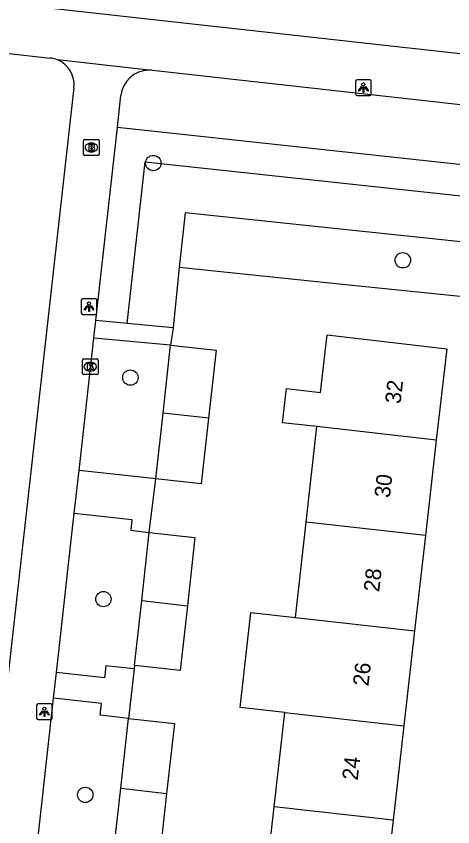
# Model space of a CAD drawing. Extents: x 161928 to 163055, y 386475 to 387428.
# Drawn here: x 162152.3 to 162180.1, y 387186 to 387237.6 of the extents above; entities that cross this region are included whole.
import ezdxf

# ---------------------------------------------------------------- set-up
doc = ezdxf.new("R2010")
doc.units = 0
for name, color, linetype in [('IMGEO_Boom', 7, 'Continuous'), ('IMGEO_Brandkraan', 7, 'Continuous'), ('IMGEO_Groenvoorziening', 7, 'Continuous'), ('IMGEO_Kolk', 7, 'Continuous'), ('IMGEO_Lichtpunt', 7, 'Continuous'), ('IMGEO_Pand', 7, 'Continuous'), ('IMGEO_Pand_nummerreeks', 7, 'Continuous'), ('IMGEO_Voetpad_open', 7, 'Continuous')]:
    doc.layers.add(name, color=color, linetype=linetype)

msp = doc.modelspace()

# ---------------------------------------------------------------- linework, layer by layer
at = {"layer": 'IMGEO_Boom'}
for centre in [(162161.043, 387228.29), (162176.933, 387222.099), (162159.581, 387214.63), (162157.866, 387200.526), (162156.71, 387188.06)]:
    msp.add_circle(centre, 0.489, dxfattribs=at)
at = {"layer": 'IMGEO_Brandkraan'}
for p, q in [((162156.596, 387228.856), (162156.596, 387229.708)), ((162156.671, 387229.782), (162157.523, 387229.782)), ((162157.597, 387229.708), (162157.597, 387228.856)), ((162157.084, 387229.562), (162157.109, 387229.562)), ((162157.523, 387228.782), (162156.671, 387228.782)), ((162157.107, 387229.002), (162157.082, 387229.002))]:
    msp.add_line(p, q, dxfattribs=at)
for points in [[(162156.596, 387228.856), (162156.596, 387229.708)], [(162156.671, 387229.782), (162157.523, 387229.782)], [(162157.597, 387229.708), (162157.597, 387228.856)], [(162156.944, 387229.482), (162156.944, 387229.082), (162157.157, 387229.082)], [(162157.175, 387229.482), (162156.944, 387229.482)], [(162157.123, 387229.401), (162157.069, 387229.401), (162157.069, 387229.325)], [(162157.069, 387229.325), (162157.122, 387229.325)], [(162157.131, 387229.249), (162157.069, 387229.249), (162157.069, 387229.168)], [(162157.523, 387228.782), (162156.671, 387228.782)], [(162157.069, 387229.168), (162157.131, 387229.168)]]:
    msp.add_lwpolyline(points, dxfattribs=at)
for centre, radius, start, end in [((162156.673, 387229.706), 0.0765, 91.552, 178.448), ((162156.673, 387229.706), 0.0765, 91.552, 178.448), ((162157.521, 387229.706), 0.0765, 1.552, 88.448), ((162157.521, 387229.706), 0.0765, 1.552, 88.448), ((162157.124, 387229.363), 0.0379, 267.8285, 90.9355), ((162157.132, 387229.208), 0.0404, 269.8759, 90.5077), ((162157.179, 387229.337), 0.145, 59.4692, 91.5367), ((162157.204, 387229.384), 0.0922, 285.5137, 58.1501), ((162157.209, 387229.192), 0.105, 301.3115, 78.989), ((162156.673, 387228.858), 0.0765, 181.552, 268.448), ((162156.673, 387228.858), 0.0765, 181.552, 268.448), ((162157.163, 387229.333), 0.251, 268.6676, 293.5347), ((162157.521, 387228.858), 0.0765, 271.552, 358.448), ((162157.521, 387228.858), 0.0765, 271.552, 358.448)]:
    msp.add_arc(centre, radius, start, end, dxfattribs=at)
for centre, major_axis, ratio, start_param, end_param in [((162157.083, 387229.282), (-0.387, 0.002), 0.722429, 4.712389, 7.853982), ((162157.108, 387229.282), (-0.39, 0.002), 0.717154, 1.570796, 4.712389)]:
    msp.add_ellipse(centre, major_axis=major_axis, ratio=ratio, start_param=start_param, end_param=end_param, dxfattribs=at)
at = {"layer": 'IMGEO_Groenvoorziening'}
for points in [[(162158.758, 387230.57), (162185.033, 387227.739)], [(162159.369, 387218.082), (162160.517, 387228.37), (162184.778, 387225.755)], [(162184.468, 387222.871), (162163.073, 387225.131), (162162.684, 387221.642)], [(162162.684, 387221.642), (162162.318, 387217.795)], [(162184.099, 387219.432), (162172.479, 387220.631), (162162.684, 387221.642)], [(162159.843, 387196.299), (162159.819, 387196.084)]]:
    msp.add_lwpolyline(points, dxfattribs=at)
at = {"layer": 'IMGEO_Kolk'}
for p, q in [((162156.6, 387215.822), (162157.452, 387215.822)), ((162156.525, 387214.896), (162156.525, 387215.748)), ((162157.013, 387215.602), (162157.038, 387215.602)), ((162157.526, 387215.748), (162157.526, 387214.896)), ((162157.452, 387214.822), (162156.6, 387214.822)), ((162157.036, 387215.042), (162157.011, 387215.042))]:
    msp.add_line(p, q, dxfattribs=at)
for points in [[(162156.6, 387215.822), (162157.452, 387215.822)], [(162156.525, 387214.896), (162156.525, 387215.748)], [(162156.846, 387215.522), (162156.969, 387215.522), (162156.969, 387215.371), (162157.099, 387215.522), (162157.263, 387215.522), (162157.117, 387215.371), (162157.27, 387215.122), (162157.118, 387215.122), (162157.033, 387215.286), (162156.969, 387215.219), (162156.969, 387215.122), (162156.846, 387215.122), (162156.846, 387215.522)], [(162157.526, 387215.748), (162157.526, 387214.896)], [(162157.452, 387214.822), (162156.6, 387214.822)]]:
    msp.add_lwpolyline(points, dxfattribs=at)
for centre, start, end in [((162156.602, 387215.746), 91.552, 178.448), ((162156.602, 387215.746), 91.552, 178.448), ((162157.45, 387215.746), 1.552, 88.448), ((162157.45, 387215.746), 1.552, 88.448), ((162156.602, 387214.898), 181.552, 268.448), ((162156.602, 387214.898), 181.552, 268.448), ((162157.45, 387214.898), 271.552, 358.448), ((162157.45, 387214.898), 271.552, 358.448)]:
    msp.add_arc(centre, 0.0765, start, end, dxfattribs=at)
for centre, major_axis, ratio, start_param, end_param in [((162157.012, 387215.322), (-0.387, 0.002), 0.722429, 4.712389, 7.853982), ((162157.037, 387215.322), (-0.39, 0.002), 0.717154, 1.570796, 4.712389)]:
    msp.add_ellipse(centre, major_axis=major_axis, ratio=ratio, start_param=start_param, end_param=end_param, dxfattribs=at)
at = {"layer": 'IMGEO_Lichtpunt'}
for p, q in [((162173.926, 387233.497), (162173.926, 387232.69)), ((162173.926, 387233.497), (162173.926, 387232.69)), ((162174.828, 387233.592), (162174.02, 387233.592)), ((162174.828, 387233.592), (162174.02, 387233.592)), ((162174.922, 387232.69), (162174.922, 387233.497)), ((162174.922, 387232.69), (162174.922, 387233.497)), ((162174.02, 387232.596), (162174.828, 387232.596)), ((162174.02, 387232.596), (162174.828, 387232.596)), ((162156.454, 387219.554), (162156.454, 387218.747)), ((162156.454, 387219.554), (162156.454, 387218.747)), ((162157.356, 387219.649), (162156.548, 387219.649)), ((162157.356, 387219.649), (162156.548, 387219.649)), ((162157.45, 387218.747), (162157.45, 387219.554)), ((162157.45, 387218.747), (162157.45, 387219.554)), ((162156.548, 387218.653), (162157.356, 387218.653)), ((162156.548, 387218.653), (162157.356, 387218.653)), ((162153.609, 387193.758), (162153.609, 387192.951)), ((162153.609, 387193.758), (162153.609, 387192.951)), ((162154.511, 387193.853), (162153.703, 387193.853)), ((162154.511, 387193.853), (162153.703, 387193.853)), ((162154.605, 387192.951), (162154.605, 387193.758)), ((162154.605, 387192.951), (162154.605, 387193.758)), ((162153.703, 387192.857), (162154.511, 387192.857)), ((162153.703, 387192.857), (162154.511, 387192.857))]:
    msp.add_line(p, q, dxfattribs=at)
for points in [[(162174.3, 387233.161), (162174.339, 387233.133), (162174.151, 387232.871), (162174.113, 387232.898), (162174.3, 387233.161)], [(162174.402, 387233.113), (162174.449, 387233.113), (162174.449, 387232.791), (162174.402, 387232.791), (162174.402, 387233.113)], [(162174.512, 387233.133), (162174.55, 387233.16), (162174.737, 387232.898), (162174.698, 387232.87), (162174.512, 387233.133)], [(162156.828, 387219.218), (162156.867, 387219.19), (162156.679, 387218.928), (162156.641, 387218.955), (162156.828, 387219.218)], [(162156.93, 387219.17), (162156.977, 387219.17), (162156.977, 387218.848), (162156.93, 387218.848), (162156.93, 387219.17)], [(162157.04, 387219.19), (162157.078, 387219.217), (162157.265, 387218.955), (162157.226, 387218.927), (162157.04, 387219.19)], [(162153.983, 387193.422), (162154.022, 387193.394), (162153.834, 387193.132), (162153.796, 387193.159), (162153.983, 387193.422)], [(162154.085, 387193.374), (162154.132, 387193.374), (162154.132, 387193.052), (162154.085, 387193.052), (162154.085, 387193.374)], [(162154.195, 387193.394), (162154.233, 387193.421), (162154.42, 387193.159), (162154.381, 387193.131), (162154.195, 387193.394)]]:
    msp.add_lwpolyline(points, dxfattribs=at)
for centre in [(162174.425, 387233.295), (162156.953, 387219.352), (162154.108, 387193.556)]:
    msp.add_circle(centre, 0.0994, dxfattribs=at)
for centre, start, end in [((162174.02, 387233.497), 90, 180), ((162174.02, 387233.497), 90, 180), ((162174.828, 387233.497), 0, 90), ((162174.828, 387233.497), 0, 90), ((162174.02, 387232.69), 180, 270), ((162174.02, 387232.69), 180, 270), ((162174.828, 387232.69), 270, 0), ((162174.828, 387232.69), 270, 360), ((162156.548, 387219.554), 90, 180), ((162156.548, 387219.554), 90, 180), ((162157.356, 387219.554), 0, 90), ((162157.356, 387219.554), 0, 90), ((162156.548, 387218.747), 180, 270), ((162156.548, 387218.747), 180, 270), ((162157.356, 387218.747), 270, 0), ((162157.356, 387218.747), 270, 360), ((162153.703, 387193.758), 90, 180), ((162153.703, 387193.758), 90, 180), ((162154.511, 387193.758), 0, 90), ((162154.511, 387193.758), 0, 90), ((162153.703, 387192.951), 180, 270), ((162153.703, 387192.951), 180, 270), ((162154.511, 387192.951), 270, 0), ((162154.511, 387192.951), 270, 360)]:
    msp.add_arc(centre, 0.0946, start, end, dxfattribs=at)
at = {"layer": 'IMGEO_Pand'}
for points in [[(162171.455, 387211.508), (162169.279, 387211.752), (162169.523, 387213.93), (162171.699, 387213.686), (162172.111, 387217.354), (162179.728, 387216.468), (162179.066, 387210.654)], [(162161.664, 387212.369), (162162.146, 387216.705)], [(162162.146, 387216.705), (162165.044, 387216.382), (162164.561, 387212.039)], [(162161.198, 387208.179), (162161.664, 387212.369)], [(162164.561, 387212.039), (162161.664, 387212.369)], [(162164.561, 387212.039), (162164.096, 387207.856), (162161.198, 387208.179)], [(162170.773, 387205.433), (162171.455, 387211.508)], [(162179.066, 387210.654), (162171.455, 387211.508)], [(162179.066, 387210.654), (162178.374, 387204.581)], [(162170.091, 387199.35), (162170.773, 387205.433)], [(162178.374, 387204.581), (162170.773, 387205.433)], [(162160.302, 387200.431), (162160.785, 387204.778)], [(162160.785, 387204.778), (162163.696, 387204.454), (162163.212, 387200.099)], [(162178.374, 387204.581), (162177.68, 387198.499)], [(162159.843, 387196.299), (162160.302, 387200.431)], [(162160.302, 387200.431), (162163.212, 387200.099)], [(162163.212, 387200.099), (162162.754, 387195.975), (162159.843, 387196.299)], [(162169.413, 387193.315), (162166.583, 387193.632), (162167.259, 387199.668), (162170.091, 387199.35)], [(162170.091, 387199.35), (162177.68, 387198.499)], [(162177.68, 387198.499), (162176.993, 387192.465)], [(162168.74, 387187.309), (162169.413, 387193.315)], [(162169.413, 387193.315), (162176.993, 387192.465)], [(162158.973, 387188.489), (162159.466, 387192.927)], [(162159.466, 387192.927), (162162.384, 387192.602), (162161.89, 387188.157)], [(162176.993, 387192.465), (162176.309, 387186.46)], [(162158.516, 387184.381), (162158.973, 387188.489)], [(162158.973, 387188.489), (162161.89, 387188.157)], [(162161.89, 387188.157), (162161.434, 387184.057), (162158.516, 387184.381)], [(162168.081, 387181.436), (162168.74, 387187.309)], [(162176.309, 387186.46), (162168.74, 387187.309)], [(162176.309, 387186.46), (162175.64, 387180.588)]]:
    msp.add_lwpolyline(points, dxfattribs=at)
at = {"layer": 'IMGEO_Voetpad_open'}
for points in [[(162130.355, 387242.733), (162130.359, 387242.551), (162130.38, 387242.37), (162130.416, 387242.191), (162130.469, 387242.016), (162130.537, 387241.847), (162130.619, 387241.685), (162130.716, 387241.53), (162130.826, 387241.385), (162130.949, 387241.25), (162131.084, 387241.127), (162131.228, 387241.016), (162131.382, 387240.919), (162131.545, 387240.836), (162131.714, 387240.767), (162131.888, 387240.714), (162132.067, 387240.677), (162132.17, 387240.663), (162159.153, 387237.637), (162195.507, 387233.606), (162205.333, 387232.488), (162224.423, 387230.317)], [(162134.66, 387237.211), (162154.481, 387234.979)], [(162160.75, 387234.202), (162154.945, 387234.859)], [(162183.1, 387231.715), (162160.988, 387234.191)], [(162155.986, 387233.092), (162148.298, 387164.623)], [(162158.758, 387230.57), (162158.974, 387232.582)], [(162157.378, 387218.276), (162158.758, 387230.57)], [(162157.25, 387217.132), (162157.378, 387218.276)], [(162159.369, 387218.082), (162157.378, 387218.276)], [(162162.318, 387217.795), (162159.369, 387218.082)], [(162162.318, 387217.795), (162162.146, 387216.705)], [(162156.312, 387208.724), (162157.25, 387217.132)], [(162162.146, 387216.705), (162157.25, 387217.132)], [(162156.008, 387205.996), (162156.312, 387208.724)], [(162161.198, 387208.179), (162156.312, 387208.724)], [(162160.785, 387204.778), (162161.198, 387208.179)], [(162154.877, 387195.86), (162156.008, 387205.996)], [(162156.008, 387205.996), (162159.682, 387205.586), (162159.607, 387204.909), (162160.785, 387204.778)], [(162159.819, 387196.084), (162158.796, 387196.199), (162158.03, 387196.284), (162157.939, 387195.504), (162154.877, 387195.86)], [(162154.692, 387194.21), (162154.877, 387195.86)], [(162159.819, 387196.084), (162159.466, 387192.927)], [(162153.535, 387183.837), (162154.692, 387194.21)], [(162159.466, 387192.927), (162157.663, 387193.127), (162157.746, 387193.869), (162154.692, 387194.21)]]:
    msp.add_lwpolyline(points, dxfattribs=at)
for centre, radius, start, end in [((162154.279, 387233.241), 1.749, 67.6259, 83.3738), ((162154.288, 387233.282), 1.708, 353.6119, 67.3957), ((162160.785, 387232.38), 1.822, 91.1068, 173.633), ((162160.775, 387232.171), 2.031, 83.9916, 90.716)]:
    msp.add_arc(centre, radius, start, end, dxfattribs=at)

# ---------------------------------------------------------------- texts
at = {"layer": 'IMGEO_Pand_nummerreeks'}
for s, rotation, p in [('32', 83.4971, (162176.788, 387212.932)), ('30', 83.4993, (162176.107, 387206.944)), ('28', 83.4993, (162175.424, 387200.95)), ('26', 83.4993, (162174.74, 387194.953)), ('24', 83.4993, (162174.057, 387188.959))]:
    msp.add_text(s, height=1, rotation=rotation, dxfattribs=at).set_placement(p)

doc.saveas('drawing.dxf')
